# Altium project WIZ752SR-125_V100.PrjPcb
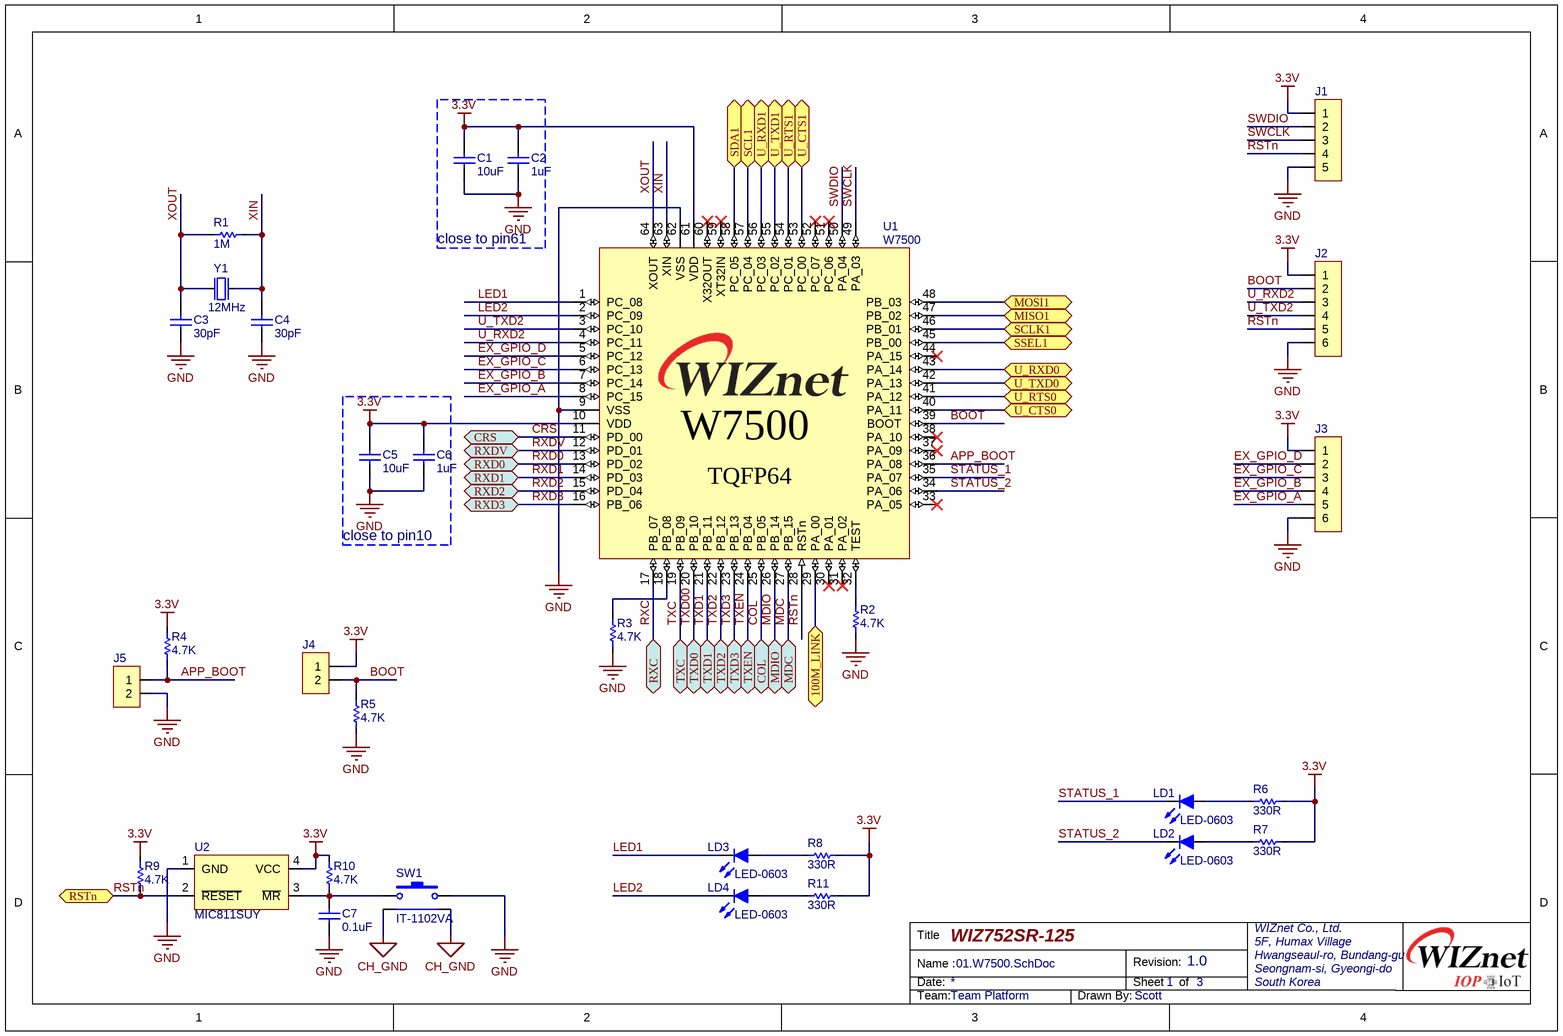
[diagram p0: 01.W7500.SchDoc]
3 sheets, 104 parts. Net scope: flat (ports and power ports of the same name join across sheets).
Board file: WIZ752SR-125_V100.PcbDoc
Sheets:
  01.W7500.SchDoc
  02.IP101GRI.SchDoc
  03.ETC.SchDoc

## Sheet 01.W7500.SchDoc: WIZ752SR-125
size A4; DrawnBy: Scott; Organization: WIZnet Co., Ltd.; Address1: 5F, Humax Village; Address2: Hwangseaul-ro, Bundang-Gu; Address3: Seongnam-Si, Gyeonggi-Do; Address4: South Korea; Revision: 1.0; SheetNumber: 1; SheetTotal: 3; Team: Team Platform

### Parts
C1  10uF  [CAP-1206]
C2  1uF  [CAP-0603]
C3  30pF  [CAP-0603]
C4  30pF  [CAP-0603]
C5  10uF  [CAP-1206]
C6  1uF  [CAP-0603]
C7  0.1uF  [CAP-0603]
J1  1.27mm 1x5 Pin Header DIP  [IDC-1X5(1.27MM)]  (value not drawn)
J2  2.54mm 1x6 Pin Header DIP  [IDC-1X6]  (value not drawn)
J3  2.54mm 1x6 Pin Header DIP  [IDC-1X6]  (value not drawn)
J4  2.54mm 1x2 Pin Header DIP  [IDC-1X2]  (value not drawn)
J5  2.54mm 1x2 Pin Header DIP  [IDC-1X2]  (value not drawn)
LD1  LED-0603  [LED-0603-RED]
LD2  LED-0603  [LED-0603-RED]
LD3  LED-0603  [LED-0603-RED]
LD4  LED-0603  [LED-0603-RED]
R1  1M  [RES-0603]
R2  4.7K  [RES-0603]
R3  4.7K  [RES-0603]
R4  4.7K  [RES-0603]
R5  4.7K  [RES-0603]
R6  330R  [RES-0603]
R7  330R  [RES-0603]
R8  330R  [RES-0603]
R9  4.7K  [RES-0603]
R10  4.7K  [RES-0603]
R11  330R  [RES-0603]
SW1  IT-1102VA  [IT-1102VA]
U1  W7500  [W7500-LQFP64]
U2  MIC811SUY  [SOT-143]
Y1  12MHz  [OSC-TZ1067B]

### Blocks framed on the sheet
close to pin61: C1 C2
close to pin10: C5 C6

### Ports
100M_LINK (bidir), COL (bidir), CRS (bidir), MDC (bidir), MDIO (bidir), MISO1 (bidir), MOSI1 (bidir), RSTn (bidir), RXC (bidir), RXD0 (bidir), RXD1 (bidir), RXD2 (bidir), RXD3 (bidir), RXDV (bidir), SCL1 (bidir), SCLK1 (bidir), SDA1 (bidir), SSEL1 (bidir), TXC (bidir), TXD0 (bidir), TXD1 (bidir), TXD2 (bidir), TXD3 (bidir), TXEN (bidir), U_CTS0 (bidir), U_CTS1 (bidir), U_RTS0 (bidir), U_RTS1 (bidir), U_RXD0 (bidir), U_RXD1 (bidir), U_TXD0 (bidir), U_TXD1 (bidir)

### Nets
3.3V: C1.2 C2.2 C5.2 C6.2 J1.1 J2.1 J3.1 J4.1 R4.2 R6.2 R7.2 R8.2 R9.2 R10.2 R11.2 U1.10(VDD) U1.61(VDD) U2.4(VCC)
CH_GND: SW1.3 SW1.4
GND: C1.1 C2.1 C3.1 C4.1 C5.1 C6.1 C7.2 J1.5 J2.6 J3.6 J5.2 R2.1 R3.1 R5.1 SW1.2 U1.9(VSS) U1.62(VSS) U2.1(GND) Y1.2 Y1.4
APP_BOOT: J5.1 R4.1 U1.36(PA_08)
BOOT: J2.2 J4.2 R5.2 U1.39(BOOT)
COL: U1.25(PB_05) ; port COL
CRS: U1.11(PD_00) ; port CRS
EX_GPIO_A: J3.5 U1.8(PC_15)
EX_GPIO_B: J3.4 U1.7(PC_14)
EX_GPIO_C: J3.3 U1.6(PC_13)
EX_GPIO_D: J3.2 U1.5(PC_12)
LED1: LD3.2(K) U1.1(PC_08)
LED2: LD4.2(K) U1.2(PC_09)
MDC: U1.27(PB_15) ; port MDC
MDIO: U1.26(PB_14) ; port MDIO
PHY_AD0: U1.29(PA_00) ; port 100M_LINK
RSTn: J1.4 J2.5 R9.1 U1.28(RSTn) U2.2(~{RESET}) ; port RSTn
RXC: U1.17(PB_07) ; port RXC
RXD0: U1.13(PD_02) ; port RXD0
RXD1: U1.14(PD_03) ; port RXD1
RXD2: U1.15(PD_04) ; port RXD2
RXD3: U1.16(PB_06) ; port RXD3
RXDV: U1.12(PD_01) ; port RXDV
STATUS_1: LD1.2(K) U1.35(PA_07)
STATUS_2: LD2.2(K) U1.34(PA_06)
SWCLK: J1.3 U1.49(PA_03)
SWDIO: J1.2 U1.50(PA_04)
TXC: U1.19(PB_09) ; port TXC
TXD00: U1.20(PB_10) ; port TXD0
TXD1: U1.21(PB_11) ; port TXD1
TXD2: U1.22(PB_12) ; port TXD2
TXD3: U1.23(PB_13) ; port TXD3
TXEN: U1.24(PB_04) ; port TXEN
U_RXD2: J2.3 U1.4(PC_11)
U_TXD2: J2.4 U1.3(PC_10)
XIN: C4.2 R1.1 U1.63(XIN) Y1.3(out)
XOUT: C3.2 R1.2 U1.64(XOUT) Y1.1(inp)
NetC7_1: C7.1 R10.1 SW1.1 U2.3(~{MR})
NetLD1_1: LD1.1(A) R6.1
NetLD2_1: LD2.1(A) R7.1
NetLD3_1: LD3.1(A) R8.1
NetLD4_1: LD4.1(A) R11.1
NetR2_2: R2.2 U1.32(TEST)
NetR3_2: R3.2 U1.18(PB_08)
NetR24_1: U1.45(PB_00) ; port SSEL1
NetR25_1: U1.58(PC_05) ; port SDA1
NetR26_1: U1.57(PC_04) ; port SCL1
NetU1_40: U1.40(PA_11) ; port U_CTS0
NetU1_41: U1.41(PA_12) ; port U_RTS0
NetU1_42: U1.42(PA_13) ; port U_TXD0
NetU1_43: U1.43(PA_14) ; port U_RXD0
NetU1_46: U1.46(PB_01) ; port SCLK1
NetU1_47: U1.47(PB_02) ; port MISO1
NetU1_48: U1.48(PB_03) ; port MOSI1
NetU1_53: U1.53(PC_00) ; port U_CTS1
NetU1_54: U1.54(PC_01) ; port U_RTS1
NetU1_55: U1.55(PC_02) ; port U_TXD1
NetU1_56: U1.56(PC_03) ; port U_RXD1

Not connected (* = marked no-connect by the designer): U1 30(PA_01)* 31(PA_02)* 33(PA_05)* 37(PA_09)* 38(PA_10)* 44(PA_15)* 51(PC_06)* 52(PC_07)* 59(XT32IN)* 60(X32OUT)*

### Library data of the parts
C1 C5 = CAP-1206: Ceramic CAP 1206(3216)
C2-C4 C6 C7 = CAP-0603: Ceramic CAP 0603(1608)
R1-R11 = RES-0603: RES0603
SW1 = IT-1102VA: IT-1102VA-3.85MM
U1 = W7500: WIZnet ARM Cortex-M0
U2 = MIC811SUY: Microprocessor Reset Circuits
Y1 = OSC-TZ1067B-12MHz: X-tal 12MHz,3.2x2.5 SMD, CL=20pF

## Sheet 02.IP101GRI.SchDoc: WIZ752SR-125
size A4; DrawnBy: Scott; Organization: WIZnet Co., Ltd.; Address1: 5F, Humax Village; Address2: Hwangseaul-ro, Bundang-Gu; Address3: Seongnam-Si, Gyeonggi-Do; Address4: South Korea; Revision: 1.0; SheetNumber: 2; SheetTotal: 3; Team: Team Platform
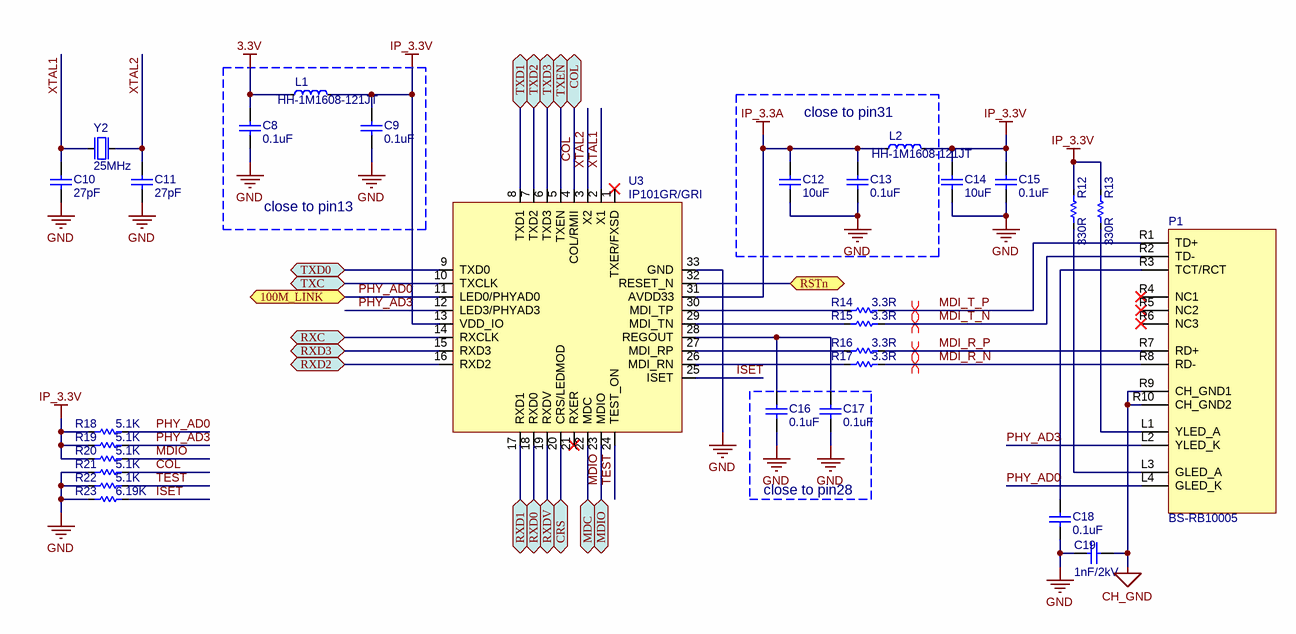
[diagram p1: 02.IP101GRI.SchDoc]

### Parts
C8  0.1uF  [CAP-0603]
C9  0.1uF  [CAP-0603]
C10  27pF  [CAP-0603]
C11  27pF  [CAP-0603]
C12  10uF  [CAP-1206]
C13  0.1uF  [CAP-0603]
C14  10uF  [CAP-1206]
C15  0.1uF  [CAP-0603]
C16  0.1uF  [CAP-0603]
C17  0.1uF  [CAP-0603]
C18  0.1uF  [CAP-0603]
C19  1nF/2kV  [CAP-1808]
L1  HH-1M1608-121JT  [IND-0603]
L2  HH-1M1608-121JT  [IND-0603]
P1  BS-RB10005  [RJ45-RB10005]
R12  330R  [RES-0603]
R13  330R  [RES-0603]
R14  3.3R  [RES-0603]
R15  3.3R  [RES-0603]
R16  3.3R  [RES-0603]
R17  3.3R  [RES-0603]
R18  5.1K  [RES-0603]
R19  5.1K  [RES-0603]
R20  5.1K  [RES-0603]
R21  5.1K  [RES-0603]
R22  5.1K  [RES-0603]
R23  6.19K  [RES-0603]
U3  IP101GR/GRI  [QFN32(0.4/4X4)]
Y2  25MHz  [OSC-82J0626]

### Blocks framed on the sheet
close to pin13: C8 C9 L1
close to pin31: C12 C13 L2
close to pin28: C16 C17

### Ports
100M_LINK (bidir), COL (bidir), CRS (bidir), MDC (bidir), MDIO (bidir), RSTn (bidir), RXC (bidir), RXD0 (bidir), RXD1 (bidir), RXD2 (bidir), RXD3 (bidir), RXDV (bidir), TXC (bidir), TXD0 (bidir), TXD1 (bidir), TXD2 (bidir), TXD3 (bidir), TXEN (bidir)

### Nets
3.3V: C8.2 L1.1
CH_GND: C19.2 P1.R9(CH_GND1) P1.R10(CH_GND2)
GND: C8.1 C9.1 C10.1 C11.1 C12.1 C13.1 C14.1 C15.1 C16.1 C17.1 C18.1 C19.1 R21.2 R22.2 R23.2 U3.33(GND) Y2.2(GND) Y2.4(GND)
IP_3.3A: C12.2 C13.2 L2.1 U3.31(AVDD33)
IP_3.3V: C9.2 C14.2 C15.2 L1.2 L2.2 R12.1 R13.1 R18.2 R19.2 R20.2 U3.13(VDD_IO)
COL: R21.1 U3.4(COL/RMII) ; port COL
CRS: U3.20(CRS/LEDMOD) ; port CRS
ISET: R23.1 U3.25(ISET)
MDC: U3.22(MDC) ; port MDC
MDI_R_N: P1.R8(RD-) R17.1
MDI_R_P: P1.R7(RD+) R16.1
MDI_T_N: P1.R2(TD-) R15.1
MDI_T_P: P1.R1(TD+) R14.1
MDIO: R20.1 U3.23(MDIO) ; port MDIO
PHY_AD0: P1.L4(GLED_K) R18.1 U3.11(LED0/PHYAD0) ; port 100M_LINK
PHY_AD3: P1.L2(YLED_K) R19.1 U3.12(LED3/PHYAD3)
RSTn: U3.32(RESET_N) ; port RSTn
RXC: U3.14(RXCLK) ; port RXC
RXD0: U3.18(RXD0) ; port RXD0
RXD1: U3.17(RXD1) ; port RXD1
RXD2: U3.16(RXD2) ; port RXD2
RXD3: U3.15(RXD3) ; port RXD3
RXDV: U3.19(RXDV) ; port RXDV
TEST: R22.1 U3.24(TEST_ON)
TXC: U3.10(TXCLK) ; port TXC
TXD00: U3.9(TXD0) ; port TXD0
TXD1: U3.8(TXD1) ; port TXD1
TXD2: U3.7(TXD2) ; port TXD2
TXD3: U3.6(TXD3) ; port TXD3
TXEN: U3.5(TXEN) ; port TXEN
XTAL1: C10.2 U3.2(X1) Y2.1(inp)
XTAL2: C11.2 U3.3(X2) Y2.3(out)
NetC16_2: C16.2 C17.2 U3.28(REGOUT)
NetC18_2: C18.2 P1.R3(TCT/RCT)
NetP1_L1: P1.L1(YLED_A) R13.2
NetP1_L3: P1.L3(GLED_A) R12.2
NetR14_2: R14.2 U3.30(MDI_TP)
NetR15_2: R15.2 U3.29(MDI_TN)
NetR16_2: R16.2 U3.27(MDI_RP)
NetR17_2: R17.2 U3.26(MDI_RN)

Not connected (* = marked no-connect by the designer): P1 R4(NC1)* R5(NC2)* R6(NC3)*; U3 1(TXER/FXSD)* 21(RXER)*

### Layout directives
differential pair: MDI_R_N, MDI_R_P, MDI_T_N, MDI_T_P

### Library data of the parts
C8-C11 C13 C15-C18 = CAP-0603: Ceramic CAP 0603(1608)
C12 C14 = CAP-1206: Ceramic CAP 1206(3216)
C19 = CAP-1808: Ceramic CAP 1808(4520)
L1 L2 = IND-0603: Inductor 0603(1608)
P1 = RB1-125BAG1A: 10/100 BASE-TX MAGJACK
R12-R23 = RES-0603: RES0603
U3 = IP101GR/GRI: Pakage: VQFN-32
Y2 = OSC-82J0626-25MHz: X-tal 25MHz,3.2x2.5 SMD, CL=18pF

## Sheet 03.ETC.SchDoc: WIZ752SR-120
size A4; DrawnBy: Scott; Organization: WIZnet Co., Ltd.; Address1: 5F, Humax Village; Address2: Hwangseaul-ro, Bundang-Gu; Address3: Seongnam-Si, Gyeonggi-Do; Address4: South Korea; Revision: 1.0; SheetNumber: 3; SheetTotal: 3; Team: Team Platform
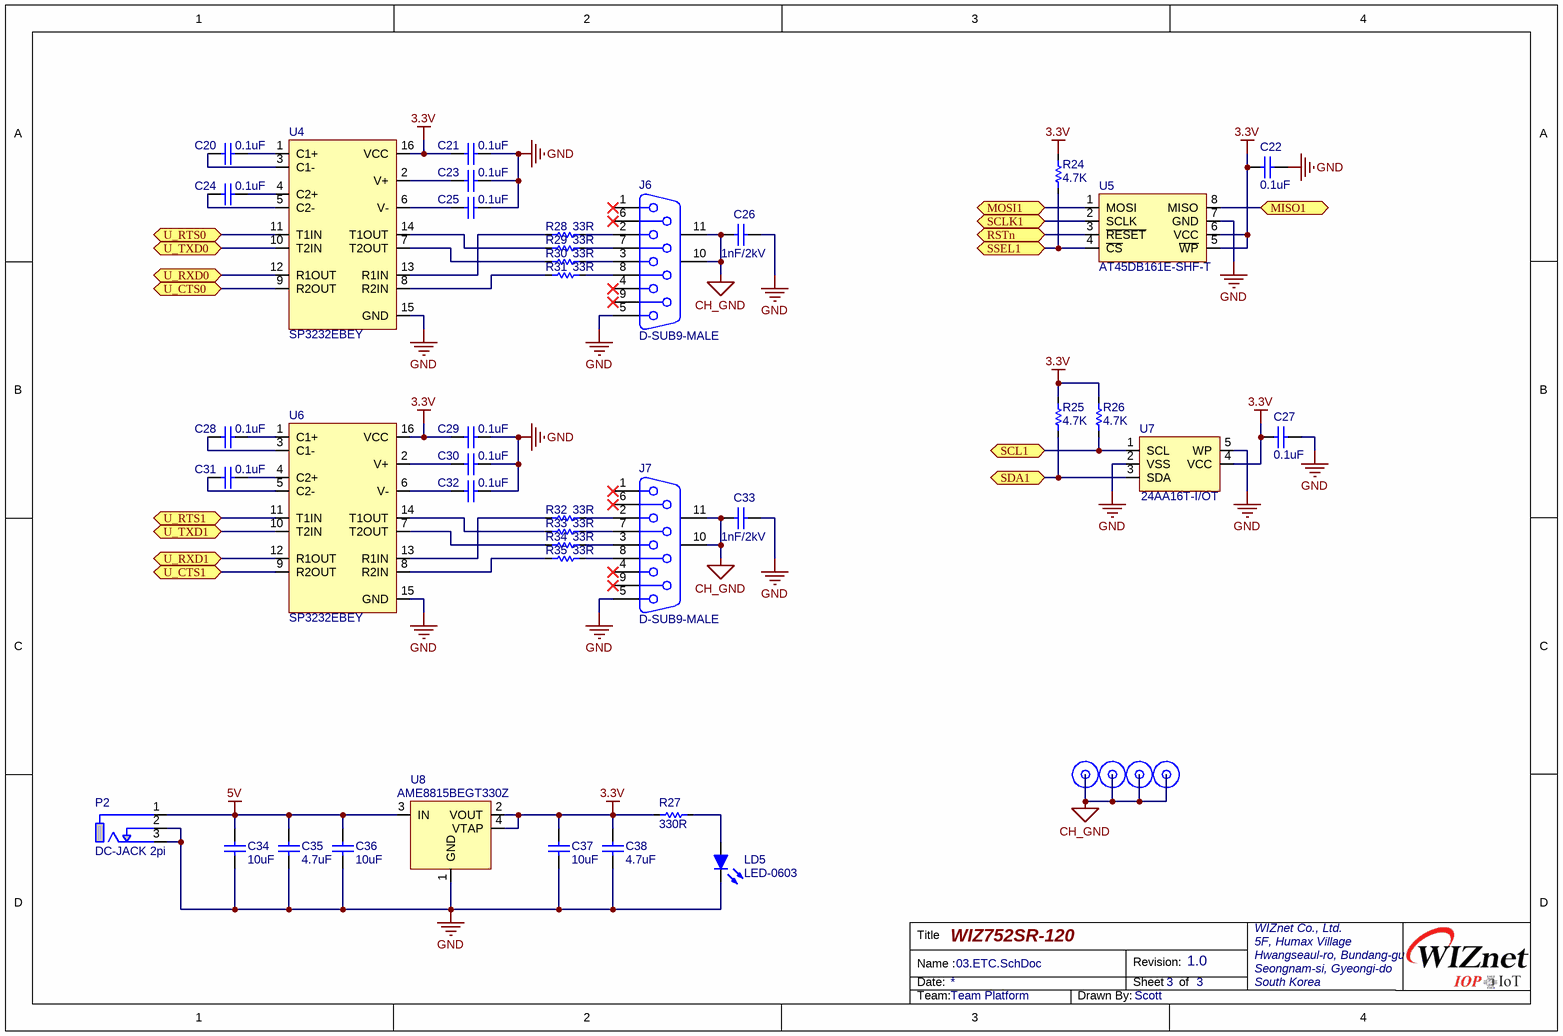
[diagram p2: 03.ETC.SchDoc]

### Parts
C20  0.1uF  [CAP-0603]
C21  0.1uF  [CAP-0603]
C22  0.1uF  [CAP-0603]
C23  0.1uF  [CAP-0603]
C24  0.1uF  [CAP-0603]
C25  0.1uF  [CAP-0603]
C26  1nF/2kV  [CAP-1808]
C27  0.1uF  [CAP-0603]
C28  0.1uF  [CAP-0603]
C29  0.1uF  [CAP-0603]
C30  0.1uF  [CAP-0603]
C31  0.1uF  [CAP-0603]
C32  0.1uF  [CAP-0603]
C33  1nF/2kV  [CAP-1808]
C34  10uF  [CAP-1206]
C35  4.7uF  [CAP-1206]
C36  10uF  [CAP-1206]
C37  10uF  [CAP-1206]
C38  4.7uF  [CAP-1206]
H1  PCB Hole  [HOLE-3.0/7.0]  (value not drawn)
H2  PCB Hole  [HOLE-3.0/7.0]  (value not drawn)
H3  PCB Hole  [HOLE-3.0/7.0]  (value not drawn)
H4  PCB Hole  [HOLE-3.0/7.0]  (value not drawn)
J6  D-SUB9-MALE  [D-SUB9-MALE]
J7  D-SUB9-MALE  [D-SUB9-MALE]
LD5  LED-0603  [LED-0603-RED]
P2  DC-JACK 2pi  [DC-JACK 2pi]
R24  4.7K  [RES-0603]
R25  4.7K  [RES-0603]
R26  4.7K  [RES-0603]
R27  330R  [RES-0603]
R28  33R  [RES-0603]
R29  33R  [RES-0603]
R30  33R  [RES-0603]
R31  33R  [RES-0603]
R32  33R  [RES-0603]
R33  33R  [RES-0603]
R34  33R  [RES-0603]
R35  33R  [RES-0603]
U4  SP3232EBEY  [TSSOP16(0.65/6.4)]
U5  AT45DB161E-SHF-T  [SO-08-EIAJ]
U6  SP3232EBEY  [TSSOP16(0.65/6.4)]
U7  24AA16T-I/OT  [SOT-23-5L]
U8  AME8815BEGT330Z  [SOT-223]

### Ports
MISO1 (bidir), MOSI1 (bidir), RSTn (bidir), SCL1 (bidir), SCLK1 (bidir), SDA1 (bidir), SSEL1 (bidir), U_CTS0 (bidir), U_CTS1 (bidir), U_RTS0 (bidir), U_RTS1 (bidir), U_RXD0 (bidir), U_RXD1 (bidir), U_TXD0 (bidir), U_TXD1 (bidir)

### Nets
3.3V: C21.2 C22.2 C27.2 C29.2 C37.2 C38.2 R24.2 R25.2 R26.2 R27.2 U4.16(VCC) U5.5(~{WP}) U5.6(VCC) U6.16(VCC) U7.4(VCC) U8.2(VOUT) U8.4(VTAP)
5V: C34.2 C35.2 C36.2 P2.1(VCC) U8.3(IN)
CH_GND: C26.1 C33.1 H1.1 H2.1 H3.1 H4.1 J6.10(MH1) J6.11(MH2) J7.10(MH1) J7.11(MH2)
GND: C21.1 C22.1 C23.1 C25.1 C26.2 C27.1 C29.1 C30.1 C32.1 C33.2 C34.1 C35.1 C36.1 C37.1 C38.1 J6.5 J7.5 LD5.2(K) P2.2(GND) P2.3(GND) U4.15(GND) U5.7(GND) U6.15(GND) U7.2(VSS) U7.5(WP) U8.1(GND)
RSTn: U5.3(~{RESET}) ; port RSTn
NetC20_1: C20.1 U4.1(C1+)
NetC20_2: C20.2 U4.3(C1-)
NetC23_2: C23.2 U4.2(V+)
NetC24_1: C24.1 U4.4(C2+)
NetC24_2: C24.2 U4.5(C2-)
NetC25_2: C25.2 U4.6(V-)
NetC28_1: C28.1 U6.1(C1+)
NetC28_2: C28.2 U6.3(C1-)
NetC30_2: C30.2 U6.2(V+)
NetC31_1: C31.1 U6.4(C2+)
NetC31_2: C31.2 U6.5(C2-)
NetC32_2: C32.2 U6.6(V-)
NetJ6_2: J6.2 R28.2
NetJ6_3: J6.3 R30.2
NetJ6_7: J6.7 R29.2
NetJ6_8: J6.8 R31.2
NetJ7_2: J7.2 R32.2
NetJ7_3: J7.3 R34.2
NetJ7_7: J7.7 R33.2
NetJ7_8: J7.8 R35.2
NetLD5_1: LD5.1(A) R27.1
NetR24_1: R24.1 U5.4(~{CS}) ; port SSEL1
NetR25_1: R25.1 U7.3(SDA) ; port SDA1
NetR26_1: R26.1 U7.1(SCL) ; port SCL1
NetR28_1: R28.1 U4.13(R1IN)
NetR29_1: R29.1 U4.14(T1OUT)
NetR30_1: R30.1 U4.7(T2OUT)
NetR31_1: R31.1 U4.8(R2IN)
NetR32_1: R32.1 U6.13(R1IN)
NetR33_1: R33.1 U6.14(T1OUT)
NetR34_1: R34.1 U6.7(T2OUT)
NetR35_1: R35.1 U6.8(R2IN)
NetU1_40: U4.9(R2OUT) ; port U_CTS0
NetU1_41: U4.11(T1IN) ; port U_RTS0
NetU1_42: U4.10(T2IN) ; port U_TXD0
NetU1_43: U4.12(R1OUT) ; port U_RXD0
NetU1_46: U5.2(SCLK) ; port SCLK1
NetU1_47: U5.8(MISO) ; port MISO1
NetU1_48: U5.1(MOSI) ; port MOSI1
NetU1_53: U6.9(R2OUT) ; port U_CTS1
NetU1_54: U6.11(T1IN) ; port U_RTS1
NetU1_55: U6.10(T2IN) ; port U_TXD1
NetU1_56: U6.12(R1OUT) ; port U_RXD1

Not connected (* = marked no-connect by the designer): J6 1* 4* 6* 9*; J7 1* 4* 6* 9*

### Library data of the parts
C20-C25 C27-C32 = CAP-0603: Ceramic CAP 0603(1608)
C26 C33 = CAP-1808: Ceramic CAP 1808(4520)
C34-C38 = CAP-1206: Ceramic CAP 1206(3216)
H1-H4 = PCB Hole: PCB Supporter Hole
J6 J7 = D-SUB9-MALE: D-SUB-9, MALE,  Right Angle; PackageDocument: O; Positions: 9; Gender: Receptacle
R24-R35 = RES-0603: RES0603
U4 U6 = SP3232EBEY: True +3.0V to +5.5V RS-232 Transceivers
U5 = AT45DB161E-SHF-T: 16-Mbit DataFlash, 2.3V or 2.5V Minimum SPI Serial Flash Memory
U7 = 24AAxxT-i-OT: SOT-23
U8 = AME8815BEGT330Z: 1.5A CMOS LDO

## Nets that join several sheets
3.3V: 01.W7500 (18 pins), 02.IP101GRI (C8.2 L1.1), 03.ETC (17 pins)
CH_GND: 01.W7500 (SW1.3 SW1.4), 02.IP101GRI (C19.2 P1.R9 P1.R10), 03.ETC (10 pins)
GND: 01.W7500 (20 pins), 02.IP101GRI (18 pins), 03.ETC (26 pins)
COL: 01.W7500 (U1.25), 02.IP101GRI (R21.1 U3.4)
CRS: 01.W7500 (U1.11), 02.IP101GRI (U3.20)
MDC: 01.W7500 (U1.27), 02.IP101GRI (U3.22)
MDIO: 01.W7500 (U1.26), 02.IP101GRI (R20.1 U3.23)
NetR24_1: 01.W7500 (U1.45), 03.ETC (R24.1 U5.4)
NetR25_1: 01.W7500 (U1.58), 03.ETC (R25.1 U7.3)
NetR26_1: 01.W7500 (U1.57), 03.ETC (R26.1 U7.1)
NetU1_40: 01.W7500 (U1.40), 03.ETC (U4.9)
NetU1_41: 01.W7500 (U1.41), 03.ETC (U4.11)
NetU1_42: 01.W7500 (U1.42), 03.ETC (U4.10)
NetU1_43: 01.W7500 (U1.43), 03.ETC (U4.12)
NetU1_46: 01.W7500 (U1.46), 03.ETC (U5.2)
NetU1_47: 01.W7500 (U1.47), 03.ETC (U5.8)
NetU1_48: 01.W7500 (U1.48), 03.ETC (U5.1)
NetU1_53: 01.W7500 (U1.53), 03.ETC (U6.9)
NetU1_54: 01.W7500 (U1.54), 03.ETC (U6.11)
NetU1_55: 01.W7500 (U1.55), 03.ETC (U6.10)
NetU1_56: 01.W7500 (U1.56), 03.ETC (U6.12)
PHY_AD0: 01.W7500 (U1.29), 02.IP101GRI (P1.L4 R18.1 U3.11)
RSTn: 01.W7500 (5 pins), 02.IP101GRI (U3.32), 03.ETC (U5.3)
RXC: 01.W7500 (U1.17), 02.IP101GRI (U3.14)
RXD0: 01.W7500 (U1.13), 02.IP101GRI (U3.18)
RXD1: 01.W7500 (U1.14), 02.IP101GRI (U3.17)
RXD2: 01.W7500 (U1.15), 02.IP101GRI (U3.16)
RXD3: 01.W7500 (U1.16), 02.IP101GRI (U3.15)
RXDV: 01.W7500 (U1.12), 02.IP101GRI (U3.19)
TXC: 01.W7500 (U1.19), 02.IP101GRI (U3.10)
TXD00: 01.W7500 (U1.20), 02.IP101GRI (U3.9)
TXD1: 01.W7500 (U1.21), 02.IP101GRI (U3.8)
TXD2: 01.W7500 (U1.22), 02.IP101GRI (U3.7)
TXD3: 01.W7500 (U1.23), 02.IP101GRI (U3.6)
TXEN: 01.W7500 (U1.24), 02.IP101GRI (U3.5)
